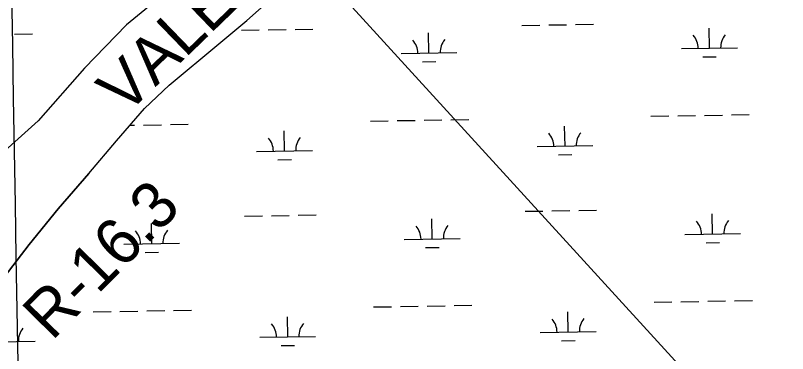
# Model space of a CAD drawing. Extents: x 3887375 to 3925618, y 296674 to 322633.
# Drawn here: x 3896776 to 3898158, y 312722 to 313327 of the extents above; entities that cross this region are included whole.
import ezdxf

# ---------------------------------------------------------------- set-up
doc = ezdxf.new("R2010")
doc.units = 0
for name, color, linetype in [('V-GRID-MAJR', 7, 'Continuous'), ('V-RIVR-EDGE', 7, 'Continuous'), ('V-RIVR-IDEN', 7, 'Continuous'), ('V-RIVR-RANG-IDEN', 7, 'Continuous'), ('V-TOPO-SHOR', 7, 'Continuous'), ('V-UTIL-LINE', 7, 'Continuous'), ('V-WETL-SWMP', 7, 'Continuous')]:
    doc.layers.add(name, color=color, linetype=linetype)

msp = doc.modelspace()

# ---------------------------------------------------------------- linework, layer by layer
at = {"layer": 'V-GRID-MAJR'}
msp.add_spline([(3896958.3310000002, 302197.087), (3896856.111, 308255.118), (3896753.858, 314315.074), (3896651.606, 320375.025), (3896651.573, 320376.956)], degree=3, dxfattribs=at)
at = {"layer": 'V-RIVR-EDGE'}
msp.add_spline([(3896115.8075614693, 312736.3390653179), (3896123.645504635, 312723.7137947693), (3896129.940618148, 312714.38723340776), (3896135.5673755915, 312703.73218250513), (3896139.52488738, 312690.4209747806), (3896139.83521988, 312681.44174761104), (3896138.156107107, 312674.7951886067), (3896136.8243285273, 312674.1334106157), (3896128.5331916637, 312683.1323720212), (3896119.587677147, 312696.45591364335), (3896111.2998293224, 312706.78500910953), (3896107.31189392, 312707.7924767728), (3896104.980870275, 312706.468098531), (3896104.302647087, 312701.14920680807), (3896107.93009214, 312688.8364218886), (3896111.2365153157, 312681.1799284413), (3896123.505720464, 312667.1830971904), (3896140.7481276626, 312647.188328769), (3896160.9586687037, 312617.2101545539), (3896188.4791912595, 312584.8861560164), (3896210.0404228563, 312563.21803064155), (3896237.5798573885, 312538.54230295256), (3896253.5077534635, 312524.8689603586), (3896271.434139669, 312512.5208182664), (3896287.7019695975, 312501.8394550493), (3896298.990841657, 312494.8282943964), (3896306.951911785, 312486.82775579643), (3896325.8306742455, 312456.1878035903), (3896335.7630999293, 312438.53885949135), (3896350.6917509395, 312424.2029166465), (3896373.5880501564, 312404.5267033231), (3896404.790286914, 312381.8371318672), (3896441.9789492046, 312359.46529324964), (3896468.8746954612, 312343.4370814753), (3896491.127306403, 312332.4083840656), (3896500.092555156, 312327.06564680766), (3896508.385336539, 312318.7317524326), (3896515.338116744, 312306.410744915), (3896528.252654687, 312284.43146478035), (3896534.8720791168, 312271.7787460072), (3896552.796820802, 312258.7655368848), (3896583.0105018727, 312239.73630087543), (3896613.555071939, 312220.041175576), (3896639.772595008, 312198.69407207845), (3896665.320939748, 312175.6859455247), (3896698.518377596, 312152.99144051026), (3896718.435853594, 312138.97569728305), (3896746.973710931, 312114.63003633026), (3896768.2056980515, 312094.2928672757), (3896793.746642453, 312068.29193908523), (3896812.6517172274, 312048.29305936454), (3896828.9006351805, 312029.9634252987), (3896844.471329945, 312006.3148995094), (3896867.3569397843, 311982.3157504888), (3896895.8898635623, 311955.9748884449), (3896948.9817541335, 311909.95370177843), (3896976.5220109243, 311885.61050760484), (3896985.1506148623, 311878.6059250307), (3896997.7729100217, 311872.9216093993), (3897005.414602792, 311870.24242930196), (3897020.0279877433, 311862.8905125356), (3897041.600730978, 311845.87785637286), (3897061.1832066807, 311830.8653348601), (3897070.144344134, 311823.8599300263), (3897078.7655477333, 311813.8625458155), (3897087.703661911, 311797.54620255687), (3897092.32952977, 311785.5634843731), (3897096.9636202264, 311776.906101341), (3897111.2115812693, 311756.25366622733), (3897119.502718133, 311747.2547048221), (3897129.4573448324, 311738.5841656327), (3897149.3698872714, 311722.5732213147), (3897170.9401637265, 311704.5629646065), (3897186.2021705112, 311690.5587330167), (3897201.7810878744, 311670.2355423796), (3897228.6250317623, 311633.25771914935), (3897264.7437346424, 311581.62539797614), (3897279.999163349, 311564.96089826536), (3897305.2100410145, 311539.95839288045), (3897328.427362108, 311515.6258880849), (3897360.94246547, 311485.9498237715), (3897388.807033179, 311458.28047218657), (3897419.340913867, 311434.2624111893), (3897433.937853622, 311420.25982411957), (3897454.4916175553, 311394.60376334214), (3897475.043736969, 311368.2826355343), (3897490.6390995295, 311354.61011520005), (3897505.558705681, 311336.61630368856), (3897515.8253093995, 311319.6316043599), (3897527.761158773, 311305.3030618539), (3897546.6736338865, 311288.2969837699), (3897564.6115317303, 311280.6043108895), (3897578.222382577, 311271.25965981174), (3897592.820966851, 311257.92213977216), (3897613.057820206, 311238.5850380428), (3897630.301049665, 311218.9228031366), (3897644.5547665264, 311200.5981026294), (3897648.867835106, 311196.59701106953), (3897654.8517938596, 311195.91714336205), (3897664.8080650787, 311187.91167120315), (3897681.400205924, 311173.90415057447), (3897695.9881008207, 311156.2436948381), (3897728.1624480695, 311123.2431176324), (3897747.7227227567, 311099.2521912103), (3897753.6811914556, 311088.26378453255), (3897756.6674150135, 311085.5961160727), (3897762.6464402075, 311082.9210472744), (3897779.5678255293, 311067.5825703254), (3897798.4712557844, 311046.91862357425), (3897815.3852407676, 311028.5873449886), (3897831.9773816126, 311014.5798243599), (3897852.225746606, 310999.8981918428), (3897867.8194646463, 310985.56060447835), (3897880.750447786, 310970.231994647), (3897893.9999860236, 310949.2494927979), (3897907.5828800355, 310928.59870220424), (3897922.1641968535, 310908.27797834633), (3897948.0310966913, 310879.615959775), (3897967.2613046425, 310856.6234561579), (3897987.8257579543, 310835.2903310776), (3898011.7139018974, 310813.2839163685), (3898048.5560522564, 310785.25983025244), (3898064.4905264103, 310774.24675578), (3898081.4127339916, 310759.240812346), (3898099.651919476, 310738.91104362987), (3898112.91790291, 310724.5792120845), (3898123.186973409, 310708.5921133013), (3898130.8048206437, 310696.2694612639), (3898136.7723342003, 310688.9389232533), (3898147.3846275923, 310677.2739379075), (3898159.9888330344, 310664.2738849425), (3898168.945036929, 310655.2732790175), (3898196.4672040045, 310623.61434751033), (3898206.0753187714, 310609.291560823), (3898214.03474438, 310600.62595519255), (3898230.2828400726, 310581.9637876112), (3898242.212933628, 310565.3075104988), (3898262.438275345, 310541.3149395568), (3898281.6758836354, 310521.3152375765), (3898296.6020678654, 310505.98169418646), (3898340.4085100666, 310470.29206976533), (3898350.024847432, 310459.2946182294), (3898356.9735163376, 310445.310943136), (3898373.552501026, 310425.98288626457), (3898390.138886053, 310409.64763102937), (3898399.4374905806, 310404.6366050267), (3898413.3808749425, 310395.29113168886), (3898421.6744785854, 310387.2897708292), (3898429.9664377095, 310378.6233429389), (3898436.5792840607, 310363.3103560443), (3898463.4437844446, 310334.64587069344), (3898482.3488592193, 310314.646990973), (3898496.60750964, 310298.31749155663), (3898513.1881388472, 310279.6545017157), (3898535.738748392, 310254.6585744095), (3898547.3461755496, 310241.9935217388), (3898560.27222513, 310224.66971081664), (3898576.512920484, 310203.01474159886), (3898592.1041717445, 310187.679553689), (3898611.3376687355, 310166.01718413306), (3898633.549988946, 310138.6943444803), (3898638.1947687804, 310134.3598971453), (3898642.5144154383, 310133.0190737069), (3898652.1447312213, 310127.67469192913), (3898657.787933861, 310123.6703113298), (3898665.4164704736, 310115.6705949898), (3898676.6880750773, 310101.6762305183), (3898685.971878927, 310090.6796012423), (3898692.6093930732, 310085.342619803), (3898699.247729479, 310080.33817187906), (3898707.868110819, 310070.008254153), (3898714.4850684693, 310056.3579348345), (3898718.4442247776, 310043.7117941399), (3898720.43284779, 310041.04659245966), (3898727.404539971, 310036.3738557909), (3898760.272733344, 310015.0103070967), (3898774.2169399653, 310005.9973672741), (3898785.4943003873, 309994.3307374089), (3898801.4041067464, 309973.3416574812), (3898808.685309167, 309959.3571601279), (3898822.609781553, 309942.36341594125), (3898837.8627434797, 309924.70131568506), (3898844.8253908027, 309916.37071034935), (3898858.7490409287, 309899.04443264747), (3898871.351601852, 309885.3793126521), (3898894.5426106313, 309850.4057353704), (3898899.8541020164, 309846.7347105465), (3898908.4851727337, 309840.7277285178), (3898917.1244660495, 309838.0460816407), (3898920.4440453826, 309835.71012443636), (3898928.060248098, 309822.7224053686), (3898935.3513176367, 309812.7283101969), (3898943.639987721, 309802.7317482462), (3898951.916323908, 309787.747183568), (3898962.852105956, 309772.4235072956), (3898972.4585762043, 309757.4356535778), (3898979.0969126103, 309752.4312056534), (3898987.0694943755, 309749.08613626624), (3898990.7174959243, 309745.0866892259), (3899001.9808779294, 309727.76698960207), (3899013.2565938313, 309715.4352927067), (3899031.16653484, 309696.43648031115), (3899044.7601182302, 309680.1086254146), (3899055.6975447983, 309665.4500161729), (3899064.9797041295, 309653.78831986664), (3899074.589463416, 309640.13060020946), (3899085.5400461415, 309630.79252721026), (3899093.846805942, 309628.11170259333), (3899099.1673421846, 309628.09854643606), (3899103.152810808, 309626.09347822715), (3899108.1161457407, 309616.1051388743), (3899114.7429705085, 309606.44522173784), (3899123.683551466, 309591.1264790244), (3899128.318464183, 309582.8016295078), (3899128.3127083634, 309580.47389490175), (3899127.6196844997, 309569.1693999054), (3899127.9439954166, 309565.84324249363), (3899132.921308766, 309561.5079728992), (3899159.7767642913, 309529.18561888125), (3899190.9559777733, 309497.18510900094), (3899204.881272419, 309480.52389832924), (3899212.171519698, 309470.19726964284), (3899224.775725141, 309457.19721667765), (3899244.679222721, 309437.5284036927), (3899252.6411151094, 309429.86039860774), (3899261.9347860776, 309422.8541715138), (3899272.5585911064, 309415.84465538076), (3899279.51877165, 309406.5164494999), (3899287.4740859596, 309396.18817629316), (3899300.0618462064, 309376.5374530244), (3899311.333450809, 309362.5430885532), (3899327.912435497, 309343.21503168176), (3899342.167796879, 309325.55539820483), (3899360.0728043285, 309304.56138471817), (3899377.311100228, 309282.9039487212), (3899414.4504269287, 309240.5800991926), (3899433.3530349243, 309219.5836189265), (3899447.280796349, 309203.92000880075), (3899464.5256703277, 309184.92284092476), (3899479.112742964, 309166.92985167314), (3899493.3697488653, 309149.9352852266)], degree=3, dxfattribs=at)
at = {"layer": 'V-TOPO-SHOR'}
for points in [[(3897089.2, 313404.19800000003), (3896975.044, 313310.389), (3896899.696, 313232.79), (3896817.17, 313138.494), (3896732.629, 313063.01300000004), (3896687.507, 313022.186)], [(3896907.6550000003, 313043.83400000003), (3896957.3310000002, 313102.386), (3897007.003, 313160.477), (3897051.48, 313202.304), (3897140.285, 313276.398), (3897190.029, 313317.813), (3897231.806, 313355.726)], [(3896907.6550000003, 313043.83400000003), (3896852.7970000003, 312981.124), (3896800.7860000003, 312917.015), (3896691.185, 312774.591)]]:
    msp.add_lwpolyline(points, dxfattribs=at)
at = {"layer": 'V-UTIL-LINE'}
msp.add_lwpolyline([(3891385.621878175, 317757.34584659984), (3896110.028, 314731.261), (3903763.48, 306349.597), (3906680.5733989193, 302363.96476002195)], dxfattribs=at)
at = {"layer": 'V-WETL-SWMP'}
for p, q in [((3897682.4121322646, 313309.04481408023), (3897714.407416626, 313309.59399783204)), ((3897730.405058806, 313309.8685897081), (3897762.4003431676, 313310.4177734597)), ((3897778.397985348, 313310.69236533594), (3897810.393269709, 313311.2415490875)), ((3897180.578095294, 313300.43107287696), (3897212.573379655, 313300.98025662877)), ((3897228.5710218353, 313301.2548485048), (3897260.566306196, 313301.80403225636)), ((3897276.5639483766, 313302.0786241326), (3897308.5592327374, 313302.62780788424)), ((3897516.169589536, 313259.754504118), (3897515.5517525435, 313295.74919979)), ((3898018.0036265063, 313268.36824532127), (3898017.385789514, 313304.36294099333)), ((3896774.72863784, 313293.4649431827), (3896806.723921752, 313294.0141269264)), ((3897968.010994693, 313267.51014570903), (3898067.9962583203, 313269.22634493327)), ((3897466.176957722, 313258.8964045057), (3897566.16222135, 313260.61260373)), ((3897504.436186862, 313244.1198338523), (3897528.432650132, 313244.5317216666)), ((3898006.270223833, 313252.7335750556), (3898030.2666871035, 313253.1454628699)), ((3897913.236046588, 313146.48128097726), (3897945.231330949, 313147.03046472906)), ((3897961.2289731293, 313147.30505660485), (3897993.2242574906, 313147.85424035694)), ((3898009.221899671, 313148.12883223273), (3898041.2171840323, 313148.67801598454)), ((3898057.214826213, 313148.95260786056), (3898089.210110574, 313149.5017916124)), ((3896981.3591227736, 313130.48605932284), (3896989.556183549, 313130.6267579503)), ((3897005.5538257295, 313130.9013498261), (3897037.549110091, 313131.45053357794)), ((3897053.5467522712, 313131.72512545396), (3897085.542036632, 313132.27430920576)), ((3897411.4020096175, 313137.8675397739), (3897443.3972939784, 313138.4167235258)), ((3897459.394936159, 313138.6913154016), (3897491.39022052, 313139.2404991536)), ((3897507.3878627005, 313139.5150910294), (3897539.3831470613, 313140.0642747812)), ((3897555.3807892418, 313140.3388666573), (3897587.3760736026, 313140.8880504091)), ((3897257.70363211, 313084.47990951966), (3897257.0857951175, 313120.4746051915)), ((3897759.537669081, 313093.093650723), (3897758.9198320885, 313129.08834639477)), ((3897709.545037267, 313092.23555111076), (3897809.5303008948, 313093.9517503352)), ((3897207.711000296, 313083.62180990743), (3897307.6962639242, 313085.3380091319)), ((3897747.804266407, 313077.45898045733), (3897771.800729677, 313077.87086827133)), ((3897245.9702294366, 313068.845239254), (3897269.966692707, 313069.25712706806)), ((3897784.107399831, 312978.0663824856), (3897816.102684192, 312978.6155662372)), ((3897186.287509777, 312967.80509002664), (3897218.2827941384, 312968.35427377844)), ((3897234.2804363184, 312968.62886565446), (3897266.2757206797, 312969.17804940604)), ((3897282.27336286, 312969.45264128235), (3897314.2686472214, 312970.0018250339)), ((3897688.121546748, 312976.4188312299), (3897720.116831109, 312976.9680149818)), ((3897736.1144732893, 312977.2426068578), (3897768.1097576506, 312977.79179060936)), ((3898023.71304099, 312935.74226247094), (3898023.0952039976, 312971.736958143)), ((3897020.0449670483, 312918.51478006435), (3897019.427130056, 312954.5094757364)), ((3897521.879004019, 312927.1285212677), (3897521.2611670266, 312963.1232169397)), ((3897973.720409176, 312934.8841628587), (3898073.705672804, 312936.60036208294)), ((3897471.886372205, 312926.27042165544), (3897571.871635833, 312927.9866208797)), ((3896970.052335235, 312917.6566804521), (3897070.0375988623, 312919.37287967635)), ((3897510.145601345, 312911.49385100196), (3897534.1420646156, 312911.90573881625)), ((3898011.979638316, 312920.1075922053), (3898035.9761015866, 312920.5194800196)), ((3897008.311564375, 312902.8801097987), (3897032.308027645, 312903.291997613)), ((3897918.9454610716, 312813.85529812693), (3897950.9407454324, 312814.40448187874)), ((3897966.938387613, 312814.6790737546), (3897998.933671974, 312815.2282575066)), ((3898014.9313141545, 312815.5028493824), (3898046.9265985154, 312816.0520331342)), ((3898062.9242406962, 312816.32662501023), (3898094.919525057, 312816.8758087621)), ((3897011.263240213, 312798.2753669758), (3897043.2585245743, 312798.8245507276)), ((3897059.2561667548, 312799.09914260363), (3897091.2514511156, 312799.64832635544)), ((3897417.111424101, 312805.24155692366), (3897449.106708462, 312805.79074067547)), ((3897465.1043506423, 312806.06533255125), (3897497.099635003, 312806.6145163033)), ((3897513.0972771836, 312806.8891081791), (3897545.0925615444, 312807.43829193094)), ((3897561.090203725, 312807.71288380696), (3897593.0854880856, 312808.26206755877)), ((3896915.27738713, 312796.62781572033), (3896947.272671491, 312797.17699947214)), ((3896963.2703136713, 312797.4515913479), (3896995.2655980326, 312798.0007751)), ((3897263.4130465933, 312751.85392666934), (3897262.795209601, 312787.8486223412)), ((3897765.247083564, 312760.46766787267), (3897764.6292465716, 312796.46236354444)), ((3897715.25445175, 312759.60956826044), (3897815.239715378, 312761.3257674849)), ((3896711.586377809, 312742.38208585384), (3896811.571641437, 312744.0982850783)), ((3897213.4204147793, 312750.9958270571), (3897313.4056784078, 312752.7120262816)), ((3897753.51368089, 312744.832997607), (3897777.510144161, 312745.24488542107)), ((3897251.67964392, 312736.2192564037), (3897275.67610719, 312736.63114421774))]:
    msp.add_line(p, q, dxfattribs=at)
for points in [[(3897089.2, 313404.19800000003), (3896975.044, 313310.39), (3896899.696, 313232.79), (3896817.17, 313138.494), (3896732.628, 313063.014)], [(3896691.185, 312774.592), (3896800.7860000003, 312917.015), (3896852.798, 312981.123), (3896907.654, 313043.833), (3896957.332, 313102.386), (3897007.003, 313160.477), (3897051.4790000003, 313202.303), (3897140.285, 313276.39900000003), (3897190.028, 313317.814), (3897231.807, 313355.726)]]:
    msp.add_lwpolyline(points, dxfattribs=at)
for centre, radius, start, end in [((3897460.926645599, 313259.2811585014), 35.24628790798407, 0.2115380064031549, 41.755196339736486), ((3897571.396236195, 313261.17731618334), 35.24628790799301, 140.21153503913, 181.75519337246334), ((3897962.76068257, 313267.8948997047), 35.24628790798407, 0.2115380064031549, 41.755196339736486), ((3898073.2302731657, 313269.79105738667), 35.24628790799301, 140.21153503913, 181.75519337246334), ((3897704.2947251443, 313092.6203051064), 35.24628790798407, 0.2115380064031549, 41.755196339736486), ((3897814.7643157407, 313094.51646278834), 35.24628790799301, 140.21153503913, 181.75519337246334), ((3897202.4606881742, 313084.0065639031), 35.24628790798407, 0.2115380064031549, 41.755196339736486), ((3897312.9302787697, 313085.90272158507), 35.24628790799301, 140.21153503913, 181.75519337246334), ((3897577.1056506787, 312928.551333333), 35.24628790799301, 140.21153503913, 181.75519337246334), ((3897968.4700970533, 312935.2689168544), 35.24628790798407, 0.2115380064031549, 41.755196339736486), ((3898078.9396876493, 312937.16507453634), 35.24628790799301, 140.21153503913, 181.75519337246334), ((3896964.8020231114, 312918.04143444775), 35.24628790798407, 0.2115380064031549, 41.755196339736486), ((3897075.2716137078, 312919.9375921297), 35.24628790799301, 140.21153503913, 181.75519337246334), ((3897466.6360600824, 312926.6551756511), 35.24628790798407, 0.2115380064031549, 41.755196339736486), ((3897820.4737302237, 312761.890479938), 35.24628790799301, 140.21153503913, 181.75519337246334), ((3897208.1701026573, 312751.3805810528), 35.24628790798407, 0.2115380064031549, 41.755196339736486), ((3897318.639693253, 312753.27673873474), 35.24628790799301, 140.21153503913, 181.75519337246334), ((3897710.004139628, 312759.99432225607), 35.24628790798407, 0.2115380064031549, 41.755196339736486), ((3896816.8056562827, 312744.6629975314), 35.24628790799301, 140.21153503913, 181.75519337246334)]:
    msp.add_arc(centre, radius, start, end, dxfattribs=at)

# ---------------------------------------------------------------- texts
at = {"layer": 'V-RIVR-IDEN'}
msp.add_text('VALER', height=82.99983200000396, rotation=44.0335697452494, dxfattribs=at).set_placement((3896973.1848222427, 313146.82268933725))
at = {"layer": 'V-RIVR-RANG-IDEN'}
msp.add_text('R-16.3', height=82.99999800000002, rotation=45.50234876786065, dxfattribs=at).set_placement((3896841.5402527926, 312743.35100096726))

doc.saveas('drawing.dxf')
